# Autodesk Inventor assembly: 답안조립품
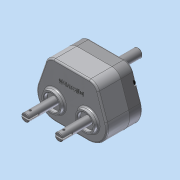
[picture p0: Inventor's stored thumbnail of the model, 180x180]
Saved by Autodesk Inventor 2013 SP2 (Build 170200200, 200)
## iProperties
Created: 2014-12
Part Number: 답안조립품
Document SubType Name: Assembly
Designer: dgall
Author: dgall
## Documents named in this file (14)
- C:\Documents and Settings\dgall\바탕 화면\441208V1043\답안조립품.iam
- C:\Documents and Settings\dgall\바탕 화면\441208V1043\본체.ipt
- C:\Documents and Settings\dgall\바탕 화면\441208V1043\M 5 x 35.ipt
- C:\Documents and Settings\dgall\바탕 화면\441208V1043\멈춤링.ipt
- C:\Documents and Settings\dgall\바탕 화면\441208V1043\메인기어.ipt
- C:\Documents and Settings\dgall\바탕 화면\441208V1043\메인축.ipt
- C:\Documents and Settings\dgall\바탕 화면\441208V1043\베어링- 6202.ipt
- C:\Documents and Settings\dgall\바탕 화면\441208V1043\베어링- 6203.ipt
- C:\Documents and Settings\dgall\바탕 화면\441208V1043\서브기어.ipt
- C:\Documents and Settings\dgall\바탕 화면\441208V1043\서브축.ipt
- C:\Documents and Settings\dgall\바탕 화면\441208V1043\오일시일-D-15.ipt
- C:\Documents and Settings\dgall\바탕 화면\441208V1043\오일시일-D-17.ipt
- C:\Documents and Settings\dgall\바탕 화면\441208V1043\커버.ipt
- C:\Documents and Settings\dgall\바탕 화면\441208V1043\키5x5.ipt
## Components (15 placed, 6 different names)
1. KS B 2023 6203 - 17 x 40 x 12:1
2. KS B 2023 6203 - 17 x 40 x 12:2
3. KS B 2023 6203 - 17 x 40 x 12:3
4. KS B 2023 6203 - 17 x 40 x 12:4
5. KS B 2023 6202 - 15 x 35 x 11:1
6. KS B 2023 6202 - 15 x 35 x 11:2
7. KS B 1336 17 x 1:1
8. KS B 1336 17 x 1:2
9. KS B 1336 17 x 1:3
10. KS B 2804 D D - 17 30 8:1
11. KS B 2804 D D - 15 30 7:1
12. KS B 2804 D D - 15 30 7:2
13. KS B 1003 - 미터 M 5 x 35:1
14. KS B 1003 - 미터 M 5 x 35:2
15. KS B 1003 - 미터 M 5 x 35:3
